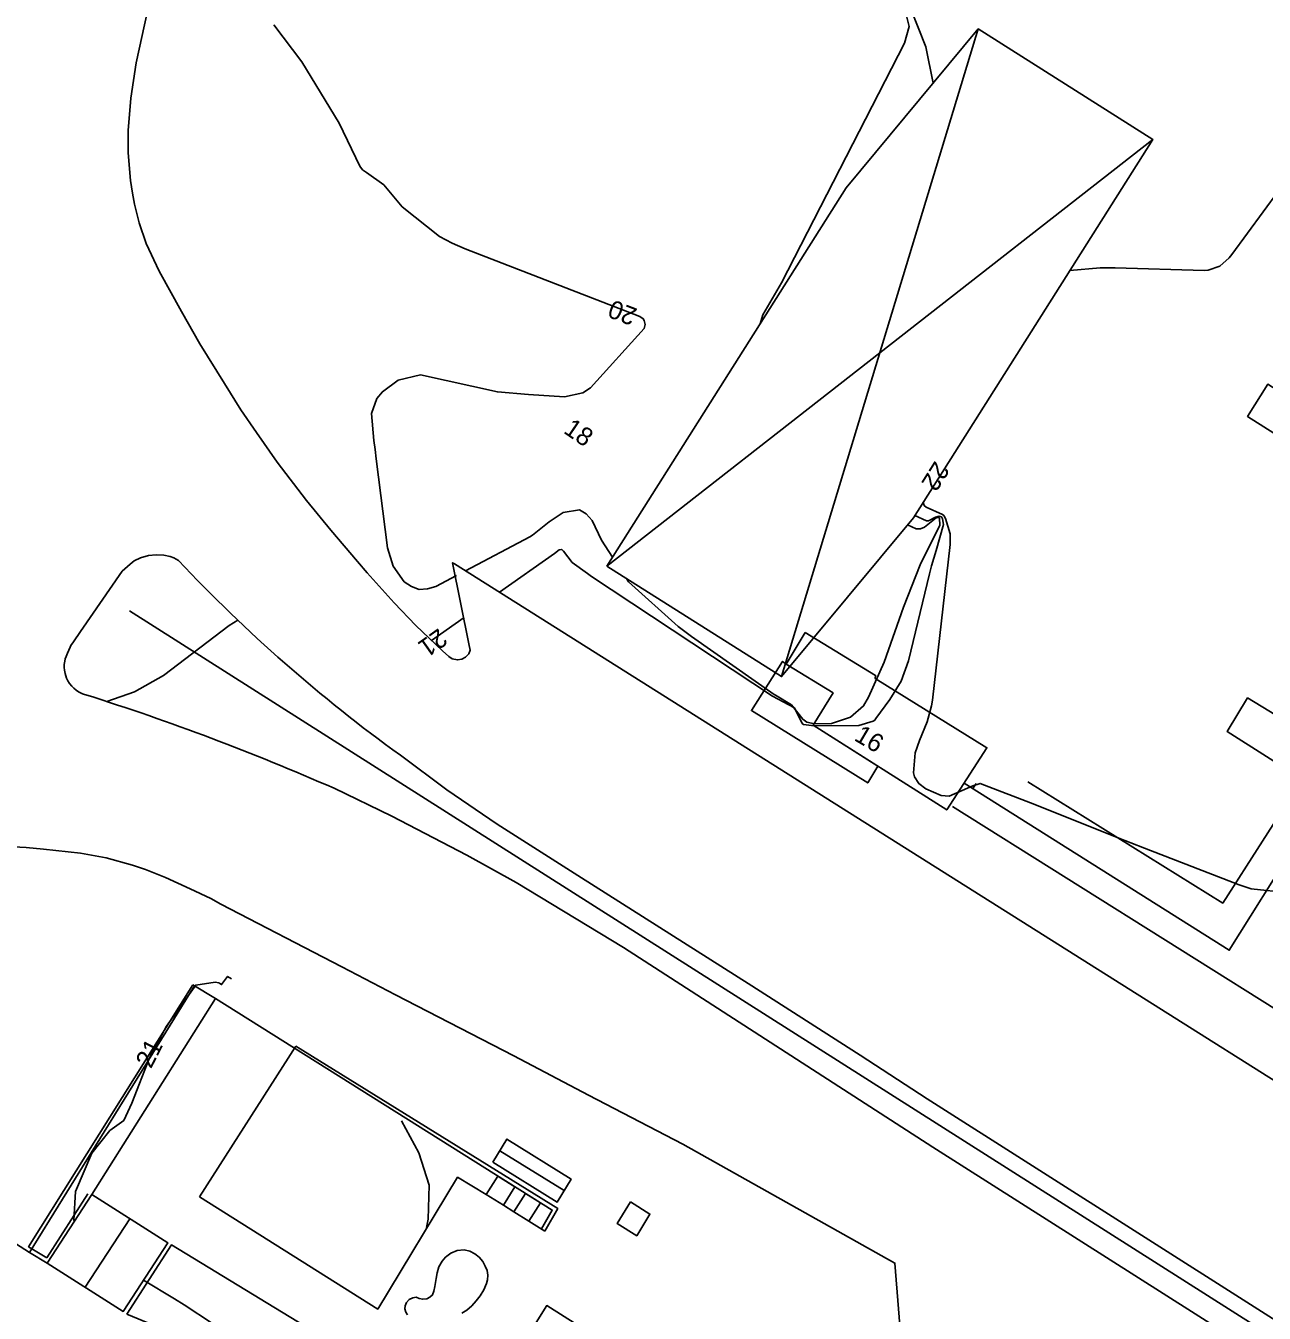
# Model space of a CAD drawing. Extents: x 67169 to 69652, y 20189 to 22818.
# Drawn here: x 69428.4 to 69496, y 21119.5 to 21189.9 of the extents above; entities that cross this region are included whole.
import ezdxf

# ---------------------------------------------------------------- set-up
doc = ezdxf.new("R2010")
doc.units = 0
for name, color, linetype in [('BYGGNAD_HUSLIV', 7, 'Continuous'), ('BYGGNAD_HUSLIV 13', 7, 'Continuous'), ('BYGGNADSDETALJER', 7, 'Continuous'), ('BYGGNADSDETALJER 19', 7, 'Continuous'), ('BYGGNADSSYMBOLER', 7, 'Continuous'), ('BYGGNADSSYMBOLER 30', 7, 'Continuous'), ('HOJDKURVOR_2014', 7, 'Continuous'), ('HOJDKURVOR_2014 5M', 7, 'Continuous'), ('HOJDKURVOR_TEXTER_2014', 7, 'Continuous'), ('Instruktioner', 7, 'Continuous'), ('MUR_STAKET', 7, 'Continuous'), ('MUR_STAKET_SYMBOL', 7, 'Continuous'), ('Std_Ritningsstämpel', 7, 'Continuous'), ('VAGAR 121', 7, 'Continuous')]:
    doc.layers.add(name, color=color, linetype=linetype)

msp = doc.modelspace()

# ---------------------------------------------------------------- linework, layer by layer
at = {"layer": 'BYGGNAD_HUSLIV'}
for points in [[(69470.951, 21156.724), (69474.797, 21154.385), (69474.778, 21154.215), (69480.88, 21150.434), (69478.688, 21147.037), (69471.381, 21151.663), (69472.473, 21153.432), (69469.915, 21155.004), (69470.951, 21156.724)], [(69474.915, 21149.418), (69471.381, 21151.663), (69472.473, 21153.432), (69469.915, 21155.004), (69469.715, 21155.15), (69468.012, 21152.464), (69474.367, 21148.514), (69474.915, 21149.418)], [(69453.888, 21127.778), (69454.647, 21129.047), (69458.154, 21126.865), (69457.395, 21125.596), (69453.888, 21127.778)], [(69455.091, 21126.445), (69454.163, 21127.028), (69453.514, 21126.013), (69454.459, 21125.43), (69455.091, 21126.445)], [(69456.495, 21125.561), (69455.672, 21126.08), (69455.03, 21125.072), (69455.856, 21124.556), (69456.495, 21125.561)]]:
    msp.add_lwpolyline(points, dxfattribs=at)
at = {"layer": 'BYGGNAD_HUSLIV 13'}
msp.add_lwpolyline([(69470.951, 21156.724), (69474.797, 21154.385), (69474.778, 21154.215), (69480.88, 21150.434), (69478.688, 21147.037), (69471.381, 21151.663), (69472.473, 21153.432), (69469.915, 21155.004), (69470.951, 21156.724)], dxfattribs=at)
at = {"layer": 'BYGGNADSDETALJER'}
msp.add_lwpolyline([(69431.972, 21126.023), (69436.128, 21123.371), (69433.685, 21119.63), (69429.524, 21122.275), (69431.972, 21126.023)], dxfattribs=at)
at = {"layer": 'BYGGNADSDETALJER 19'}
msp.add_lwpolyline([(69431.972, 21126.023), (69436.128, 21123.371), (69433.685, 21119.63), (69429.524, 21122.275), (69431.972, 21126.023)], dxfattribs=at)
at = {"layer": 'BYGGNADSSYMBOLER'}
for p, q in [((69480.406, 21189.708), (69469.659, 21154.319)), ((69460.112, 21160.362), (69489.953, 21183.664)), ((69454.268, 21128.412), (69457.775, 21126.23)), ((69431.605, 21120.953), (69434.05, 21124.697)), ((69431.604, 21120.953), (69431.604, 21120.953))]:
    msp.add_line(p, q, dxfattribs=at)
at = {"layer": 'BYGGNADSSYMBOLER 30'}
for p, q in [((69480.406, 21189.708), (69469.659, 21154.319)), ((69460.112, 21160.362), (69489.953, 21183.664))]:
    msp.add_line(p, q, dxfattribs=at)
at = {"layer": 'HOJDKURVOR_2014'}
msp.add_line((69450.534, 21156.296), (69452.314, 21157.556), dxfattribs=at)
for points in [[(69477.952, 21186.753), (69477.543, 21188.741), (69476.282, 21191.925), (69475.138, 21192.94), (69474.849, 21193.137), (69469.846, 21196.337), (69469.592, 21196.505), (69469.151, 21196.824), (69468.454, 21197.585), (69468.196, 21198.043)], [(69485.423, 21176.507), (69487.073, 21176.657), (69487.9, 21176.657), (69492.758, 21176.519), (69492.983, 21176.533), (69493.607, 21176.755), (69494.123, 21177.201), (69494.269, 21177.377), (69498.557, 21183.21), (69498.716, 21183.428), (69499.187, 21184.083), (69500.709, 21186.555), (69502.469, 21189.636), (69503.032, 21190.676)], [(69497.374, 21142.495), (69495.324, 21142.723), (69494.663, 21142.933), (69489.496, 21144.941), (69487.995, 21145.529), (69483.505, 21147.329), (69480.521, 21148.485), (69480.117, 21148.355), (69478.816, 21147.787), (69478.375, 21147.815), (69477.54, 21148.181), (69477.167, 21148.475), (69476.924, 21148.847), (69476.878, 21149.061), (69476.967, 21150.158), (69477.19, 21150.83), (69477.62, 21151.84), (69477.862, 21152.73), (69477.908, 21153.035), (69478.874, 21161.542), (69478.883, 21161.638), (69478.881, 21162.118), (69478.626, 21162.965), (69478.53, 21163.122), (69478.458, 21163.176), (69477.562, 21163.572), (69477.456, 21163.677), (69477.393, 21163.824)], [(69454.248, 21158.924), (69457.252, 21161.05), (69457.508, 21161.245), (69457.645, 21161.268), (69457.75, 21161.179), (69458.211, 21160.561), (69459.052, 21159.951), (69459.279, 21159.798), (69469.168, 21153.246), (69470.366, 21152.617), (69470.785, 21151.763), (69470.854, 21151.701), (69471.449, 21151.637), (69473.881, 21151.642), (69474.662, 21151.878), (69474.75, 21151.937), (69474.806, 21152.027), (69475.584, 21153.073), (69476.206, 21154.07), (69476.602, 21155.176), (69477.753, 21159.94), (69477.863, 21160.368), (69478.115, 21161.214), (69478.51, 21162.622), (69478.457, 21162.945), (69478.394, 21163.046), (69478.281, 21163.084), (69478.079, 21163.028), (69477.695, 21162.826), (69477.577, 21162.833), (69476.95, 21163.124)], [(69432.784, 21152.957), (69434.305, 21153.493), (69435.89, 21154.386), (69439.48, 21157.118), (69439.939, 21157.408)], [(69439.597, 21137.805), (69439.384, 21137.933), (69439.061, 21137.487), (69438.961, 21137.552), (69438.909, 21137.578), (69438.705, 21137.625), (69437.643, 21137.458), (69436.045, 21135.212), (69435.115, 21133.483), (69434.15, 21131.004), (69433.709, 21130.057), (69432.951, 21129.524), (69431.96, 21128.276), (69431.082, 21126.179), (69430.978, 21124.61), (69431, 21124.535)], [(69450.257, 21124.219), (69450.351, 21124.678), (69450.408, 21126.531), (69449.832, 21128.294), (69448.893, 21130.052)], [(69434.798, 21121.333), (69436.48, 21120.322), (69437.008, 21119.997), (69438.558, 21118.969), (69440.405, 21117.335), (69441.186, 21116.5)]]:
    msp.add_lwpolyline(points, dxfattribs=at)
at = {"layer": 'HOJDKURVOR_2014 5M'}
for points in [[(69468.492, 21173.599), (69468.639, 21174.079), (69469.653, 21175.828), (69476.382, 21188.928), (69476.634, 21189.841), (69476.201, 21191.607), (69476.099, 21191.764), (69472.791, 21194.131), (69471.962, 21194.701), (69469.888, 21196.015), (69468.979, 21196.617), (69467.944, 21197.74)], [(69441.922, 21189.934), (69443.443, 21187.908), (69445.485, 21184.56), (69446.615, 21182.217), (69446.761, 21182.007), (69446.97, 21181.859), (69447.916, 21181.19), (69448.933, 21179.988), (69450.975, 21178.373), (69451.659, 21178.006), (69452.373, 21177.686), (69461.914, 21174.003), (69462.099, 21173.872), (69462.158, 21173.778), (69462.208, 21173.552), (69462.152, 21173.337), (69459.221, 21170.1), (69458.792, 21169.833), (69457.795, 21169.603), (69455.822, 21169.735), (69454.129, 21169.876), (69449.933, 21170.807), (69448.714, 21170.51), (69447.85, 21169.882), (69447.55, 21169.521), (69447.243, 21168.688), (69447.377, 21167.22), (69447.444, 21166.72), (69447.508, 21166.22), (69448.127, 21161.348), (69448.428, 21160.348), (69449.038, 21159.5), (69449.443, 21159.237), (69449.865, 21159.087), (69450.312, 21159.108), (69450.775, 21159.243), (69451.903, 21159.84)], [(69452.388, 21160.097), (69455.895, 21161.954), (69456.041, 21162.039), (69456.964, 21162.772), (69457.729, 21163.288), (69458.62, 21163.435), (69458.986, 21163.217), (69459.312, 21162.853), (69459.82, 21161.772), (69460.422, 21160.852)], [(69461.188, 21159.681), (69461.303, 21159.505), (69464.009, 21157.057), (69464.746, 21156.514), (69469.264, 21153.348), (69469.333, 21153.302), (69470.212, 21152.773), (69470.819, 21151.993), (69471.039, 21151.833), (69471.466, 21151.746), (69472.382, 21151.758), (69473.422, 21152.095), (69474.146, 21152.721), (69474.409, 21153.198), (69475.263, 21155.109), (69476.318, 21158.12), (69477.244, 21160.433), (69478.302, 21162.594), (69478.297, 21162.978), (69478.29, 21162.995), (69478.247, 21163.019), (69478.162, 21163.016), (69478.105, 21162.998), (69477.48, 21162.477), (69477.252, 21162.395), (69477.009, 21162.402), (69476.55, 21162.614)]]:
    msp.add_lwpolyline(points, dxfattribs=at)
at = {"layer": 'MUR_STAKET'}
for p, q in [((69524.486, 21100.47), (69434.032, 21157.909)), ((69480.288, 21148.482), (69480.113, 21148.198)), ((69438.731, 21136.724), (69437.492, 21137.47)), ((69431.972, 21126.023), (69438.731, 21136.723)), ((69437.855, 21125.888), (69443.118, 21134.128)), ((69431.749, 21126.063), (69429.515, 21122.552)), ((69436.128, 21123.371), (69433.685, 21119.63))]:
    msp.add_line(p, q, dxfattribs=at)
for points in [[(69483.123, 21148.57), (69493.774, 21141.942), (69498.104, 21148.712), (69494.004, 21151.324), (69495.133, 21153.151), (69499.37, 21150.58), (69506.242, 21161.506), (69495.127, 21168.537), (69496.228, 21170.296), (69497.519, 21169.477), (69512.881, 21159.339), (69506.131, 21148.588), (69504.388, 21149.623), (69499.254, 21141.341), (69500.998, 21140.293), (69497.884, 21135.372)], [(69479.633, 21148.501), (69494.13, 21139.368), (69508.468, 21162.25)], [(69429.515, 21122.552), (69428.512, 21123.163), (69437.492, 21137.469)], [(69438.731, 21136.724), (69437.571, 21137.423), (69428.554, 21122.843)], [(69456.54, 21124.135), (69457.132, 21125.163), (69438.731, 21136.724)], [(69456.723, 21124.021), (69457.432, 21125.251), (69443.118, 21134.128)], [(69449.93, 21108.958), (69456.83, 21119.95), (69458.531, 21118.884), (69451.63, 21107.89), (69449.93, 21108.958)]]:
    msp.add_lwpolyline(points, dxfattribs=at)
at = {"layer": 'MUR_STAKET_SYMBOL'}
for p, q in [((69495.677, 21169.415), (69495.677, 21169.415)), ((69439.199, 21154.622), (69439.199, 21154.622)), ((69494.68, 21152.412), (69494.68, 21152.412)), ((69494.601, 21150.928), (69494.601, 21150.928)), ((69495.819, 21150.152), (69495.819, 21150.152)), ((69483.122, 21148.57), (69483.122, 21148.57)), ((69481.514, 21147.31), (69481.514, 21147.31)), ((69484.468, 21147.731), (69484.468, 21147.731)), ((69482.826, 21146.481), (69482.826, 21146.481)), ((69485.783, 21146.913), (69485.783, 21146.913)), ((69487.001, 21146.155), (69487.001, 21146.155)), ((69484.106, 21145.675), (69484.106, 21145.675)), ((69488.306, 21145.342), (69488.306, 21145.342)), ((69485.332, 21144.903), (69485.332, 21144.903)), ((69489.568, 21144.557), (69489.568, 21144.557)), ((69495.658, 21144.894), (69495.658, 21144.894)), ((69486.61, 21144.097), (69486.61, 21144.097)), ((69490.803, 21143.789), (69490.803, 21143.789)), ((69487.89, 21143.292), (69487.89, 21143.292)), ((69492.081, 21142.993), (69492.081, 21142.993)), ((69494.827, 21143.594), (69494.827, 21143.594)), ((69489.2, 21142.467), (69489.2, 21142.467)), ((69493.316, 21142.225), (69493.316, 21142.225)), ((69494.06, 21142.398), (69494.06, 21142.398)), ((69490.465, 21141.669), (69490.465, 21141.669)), ((69495.851, 21142.118), (69495.851, 21142.118)), ((69460.769, 21140.924), (69460.769, 21140.924)), ((69491.74, 21140.867), (69491.74, 21140.867)), ((69495.049, 21140.838), (69495.049, 21140.838)), ((69492.873, 21140.151), (69492.873, 21140.151)), ((69494.403, 21139.806), (69494.403, 21139.806)), ((69437.721, 21137.332), (69437.721, 21137.332)), ((69436.884, 21136.314), (69436.884, 21136.314)), ((69438.053, 21135.651), (69438.053, 21135.651)), ((69440.554, 21135.562), (69440.554, 21135.562)), ((69436.102, 21135.048), (69436.102, 21135.048)), ((69437.248, 21134.376), (69437.248, 21134.376)), ((69443.312, 21134.002), (69443.312, 21134.002)), ((69435.291, 21133.737), (69435.291, 21133.737)), ((69442.646, 21133.39), (69442.646, 21133.39)), ((69444.573, 21133.221), (69444.573, 21133.221)), ((69434.506, 21132.467), (69434.506, 21132.467)), ((69436.419, 21133.066), (69436.419, 21133.066)), ((69445.829, 21132.443), (69445.829, 21132.443)), ((69435.633, 21131.82), (69435.633, 21131.82)), ((69441.83, 21132.111), (69441.83, 21132.111)), ((69433.737, 21131.225), (69433.737, 21131.225)), ((69447.135, 21131.635), (69447.135, 21131.635)), ((69433.15, 21130.546), (69433.15, 21130.546)), ((69434.87, 21130.612), (69434.87, 21130.612)), ((69441.069, 21130.92), (69441.069, 21130.92)), ((69448.321, 21130.902), (69448.321, 21130.902)), ((69448.348, 21130.671), (69448.348, 21130.671)), ((69432.97, 21129.982), (69432.97, 21129.982)), ((69440.237, 21129.618), (69440.237, 21129.618)), ((69449.639, 21130.085), (69449.639, 21130.085)), ((69434.034, 21129.288), (69434.034, 21129.288)), ((69450.916, 21129.295), (69450.916, 21129.295)), ((69432.081, 21128.548), (69432.081, 21128.548)), ((69439.436, 21128.365), (69439.436, 21128.365)), ((69452.127, 21128.539), (69452.127, 21128.539)), ((69433.175, 21127.929), (69433.175, 21127.929)), ((69453.268, 21127.831), (69453.268, 21127.831)), ((69431.309, 21127.298), (69431.309, 21127.298)), ((69438.63, 21127.103), (69438.63, 21127.103)), ((69482.724, 21126.985), (69482.724, 21126.985)), ((69430.511, 21126.007), (69430.511, 21126.007)), ((69429.73, 21124.745), (69429.73, 21124.745)), ((69430.561, 21124.193), (69430.561, 21124.193)), ((69428.948, 21123.48), (69428.948, 21123.48)), ((69435.225, 21121.991), (69435.225, 21121.991))]:
    msp.add_line(p, q, dxfattribs=at)
at = {"layer": 'Std_Ritningsstämpel'}
for points in [[(69460.112, 21160.362), (69469.659, 21154.319), (69476.874, 21163.004), (69489.953, 21183.664), (69480.406, 21189.708), (69473.191, 21181.023)], [(69453.888, 21127.778), (69457.395, 21125.596), (69458.154, 21126.865), (69454.647, 21129.047)], [(69461.407, 21125.612), (69460.673, 21124.437), (69461.748, 21123.766), (69462.462, 21124.953)]]:
    msp.add_lwpolyline(points, close=True, dxfattribs=at)
at = {"layer": 'VAGAR 121'}
for p, q in [((69497.884, 21135.372), (69479.006, 21147.226)), ((69409.228, 21135.23), (69428.554, 21122.844)), ((69454.459, 21125.43), (69455.03, 21125.072)), ((69455.856, 21124.556), (69456.723, 21124.022)), ((69428.554, 21122.844), (69429.524, 21122.275))]:
    msp.add_line(p, q, dxfattribs=at)
for points in [[(69536.111, 21107.325), (69451.788, 21160.475), (69451.682, 21160.539), (69452.575, 21156.106), (69452.636, 21155.769), (69452.567, 21155.561), (69452.387, 21155.375), (69452.192, 21155.273), (69451.942, 21155.232), (69451.66, 21155.286), (69451.47, 21155.416), (69451.127, 21155.731), (69449.672, 21157.119), (69448.49, 21158.359), (69447.016, 21159.997), (69446.478, 21160.617), (69445.033, 21162.328), (69443.699, 21163.939), (69442.104, 21166.031), (69440.972, 21167.659), (69440.119, 21168.899), (69439.211, 21170.343), (69437.876, 21172.509), (69436.874, 21174.268), (69435.65, 21176.471), (69434.945, 21177.989), (69434.555, 21179.118), (69434.295, 21180.137), (69434.183, 21180.729), (69434.072, 21181.433), (69433.958, 21182.933), (69433.957, 21184.155), (69434.105, 21185.933), (69434.399, 21187.859), (69435.008, 21190.675)], [(69431.355, 21156.786), (69433.625, 21160.072), (69434.056, 21160.465), (69434.279, 21160.638), (69434.625, 21160.811), (69435.063, 21160.942), (69435.478, 21160.978), (69435.897, 21160.957), (69436.244, 21160.875), (69436.443, 21160.803), (69436.698, 21160.668)], [(69431.642, 21153.323), (69431.571, 21153.344), (69431.458, 21153.384), (69431.345, 21153.437), (69431.239, 21153.493), (69431.115, 21153.573), (69430.985, 21153.682), (69430.866, 21153.794), (69430.75, 21153.939), (69430.662, 21154.084), (69430.591, 21154.232), (69430.543, 21154.36), (69430.505, 21154.495), (69430.47, 21154.669), (69430.458, 21154.816), (69430.463, 21154.984), (69430.488, 21155.167), (69430.519, 21155.29), (69430.56, 21155.414), (69430.634, 21155.592), (69430.785, 21155.931), (69430.823, 21156.022), (69430.957, 21156.221), (69431.355, 21156.786)], [(69448.83, 21150.018), (69451.363, 21148.135), (69454.122, 21146.253), (69458.736, 21143.332), (69467.827, 21137.545), (69473.961, 21133.641), (69477.62, 21131.253)], [(69477.932, 21128.61), (69461.018, 21139.508), (69455.164, 21143.076), (69452.463, 21144.564), (69448.355, 21146.698), (69445.203, 21148.215)], [(69425.995, 21145.106), (69428.382, 21144.989), (69429.326, 21144.881), (69431.343, 21144.666), (69432.753, 21144.418), (69434.197, 21144.007), (69434.892, 21143.78), (69435.998, 21143.347), (69437.344, 21142.73), (69438.462, 21142.188), (69439.015, 21141.884), (69445.635, 21138.452), (69446.895, 21137.802), (69448.556, 21136.935), (69455.035, 21133.6), (69459.116, 21131.455), (69464.261, 21128.769), (69475.852, 21122.269), (69476.218, 21117.735)], [(69477.62, 21131.253), (69525.068, 21101.057), (69524.03, 21099.312), (69477.932, 21128.61)], [(69453.514, 21126.013), (69451.951, 21126.962), (69447.596, 21119.755), (69437.855, 21125.888)], [(69433.872, 21119.48), (69436.314, 21123.261), (69446.021, 21117.365), (69445.175, 21115.878), (69443.549, 21115.488), (69433.872, 21119.48)], [(69452.307, 21122.991), (69451.93, 21122.958), (69451.585, 21122.808), (69451.302, 21122.596), (69451.108, 21122.374), (69450.931, 21122.064), (69450.844, 21121.746), (69450.782, 21121.428), (69450.711, 21120.994), (69450.658, 21120.738), (69450.58, 21120.535), (69450.447, 21120.402), (69450.271, 21120.322), (69450.05, 21120.296), (69449.847, 21120.34), (69449.697, 21120.401), (69449.511, 21120.375), (69449.317, 21120.286), (69449.167, 21120.109), (69449.096, 21119.941), (69449.069, 21119.764), (69449.122, 21119.588), (69449.221, 21119.437)], [(69452.189, 21119.528), (69452.453, 21119.706), (69452.727, 21119.935), (69452.974, 21120.201), (69453.195, 21120.484), (69453.388, 21120.811), (69453.53, 21121.156), (69453.583, 21121.359), (69453.6, 21121.615), (69453.573, 21121.863), (69453.467, 21122.11), (69453.334, 21122.358), (69453.131, 21122.597), (69452.901, 21122.774), (69452.627, 21122.924), (69452.307, 21122.991)]]:
    msp.add_lwpolyline(points, dxfattribs=at)
for centre, radius, start, end in [((69498.544, 21218.881), 84.933, 223.26698, 234.17404), ((69392.048, 21027.655), 131.758, 66.2073, 72.51222)]:
    msp.add_arc(centre, radius, start, end, dxfattribs=at)

# ---------------------------------------------------------------- texts
at = {"layer": 'HOJDKURVOR_TEXTER_2014'}
for s, rotation, p in [('20', 158.8898, (69461.832, 21174.399)), ('22', 237.91885, (69478.051, 21166.153)), ('21', 215.28307, (69450.93, 21156.993)), ('21', 62.96296, (69435.2, 21132.855))]:
    msp.add_text(s, height=1, rotation=rotation, dxfattribs=at).set_placement(p)
at = {"layer": 'Instruktioner'}
for s, rotation, p in [('18', 325.79742, (69457.691, 21167.667)), ('16', 329.48147, (69473.572, 21150.869))]:
    msp.add_text(s, height=1, rotation=rotation, dxfattribs=at).set_placement(p)

doc.saveas('drawing.dxf')
